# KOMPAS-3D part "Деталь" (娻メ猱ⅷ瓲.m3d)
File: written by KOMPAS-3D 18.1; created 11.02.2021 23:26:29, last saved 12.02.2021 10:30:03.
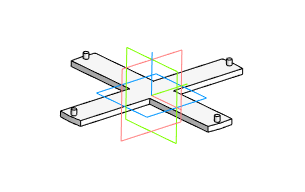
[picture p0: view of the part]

Document properties: Полное имя файла: C:\GoogleDrive\НИР\ИКИ\Компас\Крестовина.m3d

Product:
- Part/product: Деталь
    Масса: 0.160372

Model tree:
1. Эскиз:1
2. Элемент выдавливания:1
     Расстояние 1 = 4
3. Эскиз:3  (with: Элемент выдавливания:1)
4. Элемент выдавливания:4
     Расстояние 1 = 4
